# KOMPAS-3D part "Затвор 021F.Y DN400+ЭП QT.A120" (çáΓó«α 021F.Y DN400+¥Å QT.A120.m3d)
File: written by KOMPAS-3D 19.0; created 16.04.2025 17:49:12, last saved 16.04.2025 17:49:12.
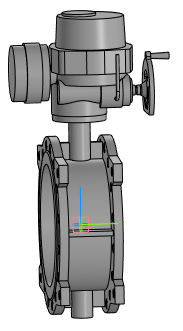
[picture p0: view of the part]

Document properties: Полное имя файла: Затвор 021F.Y DN400+ЭП QT.A120.a3d

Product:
- Part/product: Затвор 021F.Y DN400+ЭП QT.A120
    Масса: 265.394

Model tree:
1. Операция без истории:1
